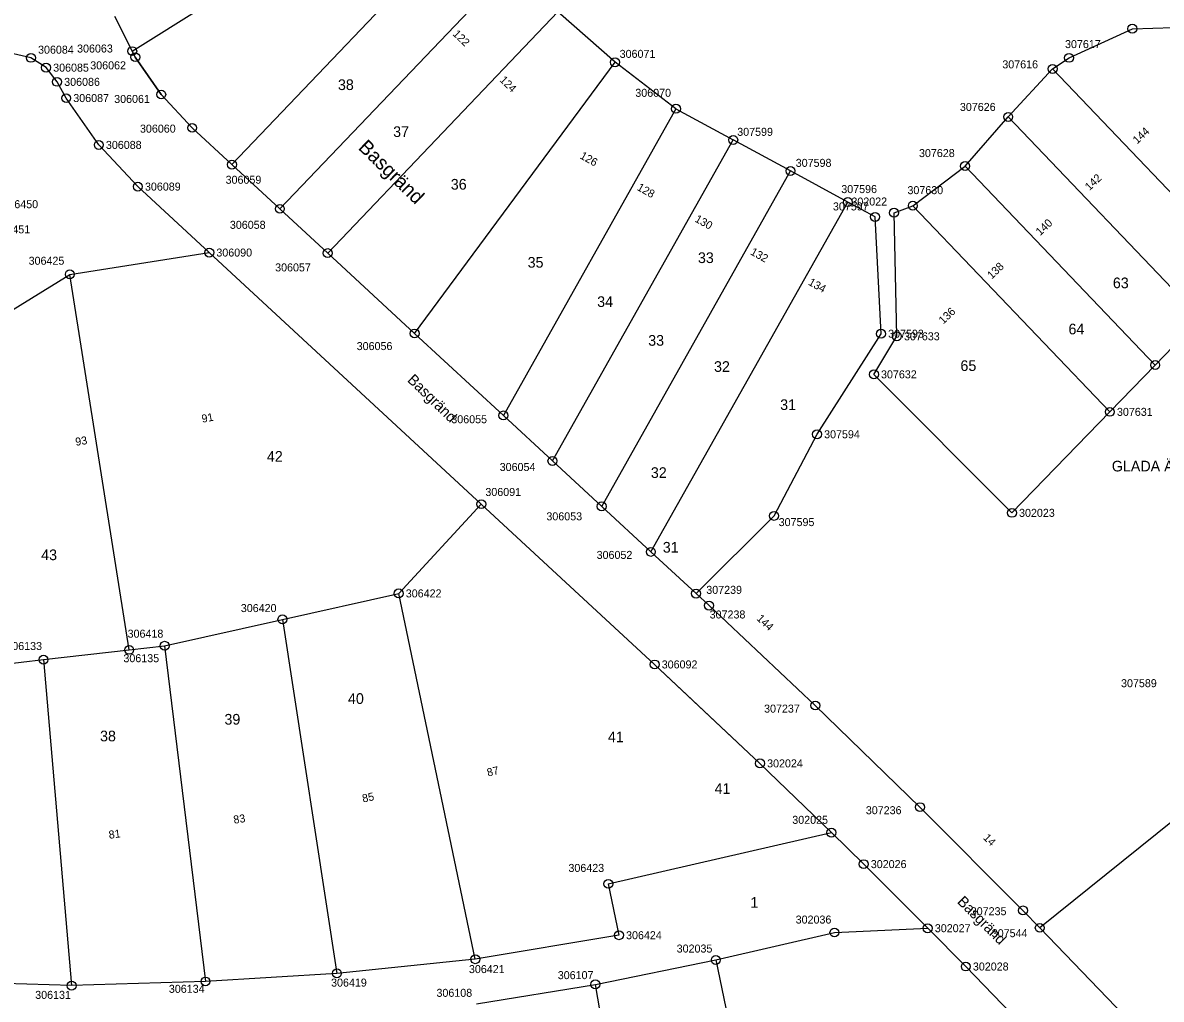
# Model space of a CAD drawing. Extents: x 141995 to 152570, y 6580184 to 6586000.
# Drawn here: x 142151.4 to 142279.5, y 6585489.3 to 6585599.2 of the extents above; entities that cross this region are included whole.
import ezdxf

# ---------------------------------------------------------------- set-up
doc = ezdxf.new("R2010")
doc.units = 0
for name, color, linetype in [('Level 10', 7, 'Continuous'), ('Level 40', 7, 'Continuous'), ('Level 42', 7, 'Continuous'), ('Level 43', 7, 'Continuous'), ('Level 5', 7, 'Continuous'), ('Level 50', 7, 'Continuous'), ('Level 51', 7, 'Continuous'), ('Level 53', 7, 'Continuous'), ('Level 54', 7, 'Continuous'), ('Level 55', 7, 'Continuous'), ('Level 59', 7, 'Continuous'), ('Level 6', 7, 'Continuous'), ('Level 7', 7, 'Continuous')]:
    doc.layers.add(name, color=color, linetype=linetype)

msp = doc.modelspace()

# ---------------------------------------------------------------- linework, layer by layer
at = {"layer": 'Level 10'}
for centre in [(142276.21, 6585598.48), (142163.75, 6585595.96), (142164.09, 6585595.28), (142152.36, 6585595.2), (142154.06, 6585594.1), (142218.04, 6585594.7), (142267.24, 6585593.96), (142269.09, 6585595.2), (142155.3, 6585592.5), (142156.32, 6585590.67), (142167.01, 6585591.08), (142224.89, 6585589.48), (142262.25, 6585588.56), (142170.49, 6585587.33), (142159.99, 6585585.41), (142231.33, 6585585.97), (142174.96, 6585583.19), (142237.77, 6585582.48), (142257.4, 6585583.03), (142164.38, 6585580.72), (142244.22, 6585578.98), (142180.35, 6585578.22), (142247.28, 6585577.31), (142249.41, 6585577.78), (142251.52, 6585578.57), (142172.41, 6585573.3), (142185.73, 6585573.24), (142156.73, 6585570.85), (142195.5, 6585564.2), (142247.95, 6585564.17), (142249.73, 6585563.88), (142247.15, 6585559.6), (142278.78, 6585560.65), (142205.48, 6585554.98), (142273.68, 6585555.38), (142240.75, 6585552.86), (142211, 6585549.86), (142203, 6585545), (142216.54, 6585544.75), (142262.67, 6585544.02), (142235.92, 6585543.68), (142222.07, 6585539.63), (142193.71, 6585534.96), (142227.15, 6585534.94), (142228.61, 6585533.59), (142180.64, 6585532.04), (142167.39, 6585529.07), (142153.77, 6585527.51), (142163.41, 6585528.61), (142222.49, 6585526.97), (142240.56, 6585522.35), (142234.34, 6585515.84), (142252.33, 6585510.92), (142242.37, 6585508.05), (142246, 6585504.51), (142217.28, 6585502.29), (142263.91, 6585499.3), (142242.71, 6585496.82), (142253.2, 6585497.29), (142265.8, 6585497.34), (142218.48, 6585496.51), (142202.33, 6585493.81), (142229.37, 6585493.73), (142257.48, 6585492.99), (142186.76, 6585492.22), (142156.93, 6585490.84), (142171.99, 6585491.31), (142215.83, 6585490.98)]:
    msp.add_circle(centre, 0.5, dxfattribs=at)
at = {"layer": 'Level 5'}
for points in [[(142163.75, 6585595.96), (142161.78, 6585599.85)], [(142164.09, 6585595.28), (142163.75, 6585595.96)], [(142152.36, 6585595.2), (142150.39, 6585595.67)], [(142154.06, 6585594.1), (142152.36, 6585595.2)], [(142167.01, 6585591.08), (142164.09, 6585595.28)], [(142155.3, 6585592.5), (142154.06, 6585594.1)], [(142156.32, 6585590.67), (142155.3, 6585592.5)], [(142159.99, 6585585.41), (142156.32, 6585590.67)], [(142170.49, 6585587.33), (142167.01, 6585591.08)], [(142174.96, 6585583.19), (142170.49, 6585587.33)], [(142164.38, 6585580.72), (142159.99, 6585585.41)], [(142180.35, 6585578.22), (142174.96, 6585583.19)], [(142172.41, 6585573.3), (142164.38, 6585580.72)], [(142185.73, 6585573.24), (142180.35, 6585578.22)], [(142172.41, 6585573.3), (142203, 6585545)], [(142195.5, 6585564.2), (142185.73, 6585573.24)], [(142205.48, 6585554.98), (142195.5, 6585564.2)], [(142211, 6585549.86), (142205.48, 6585554.98)], [(142216.54, 6585544.75), (142211, 6585549.86)], [(142203, 6585545), (142222.49, 6585526.97)], [(142222.07, 6585539.63), (142216.54, 6585544.75)], [(142222.07, 6585539.63), (142227.15, 6585534.94)], [(142228.61, 6585533.59), (142227.15, 6585534.94)], [(142240.56, 6585522.35), (142228.61, 6585533.59)], [(142222.49, 6585526.97), (142234.34, 6585515.84)], [(142252.33, 6585510.92), (142240.56, 6585522.35)], [(142234.34, 6585515.84), (142242.37, 6585508.05)], [(142263.91, 6585499.3), (142252.33, 6585510.92)], [(142246, 6585504.51), (142242.37, 6585508.05)], [(142253.2, 6585497.29), (142246, 6585504.51)], [(142265.8, 6585497.34), (142263.91, 6585499.3)], [(142253.2, 6585497.29), (142257.48, 6585492.99)], [(142275.29, 6585487.49), (142265.8, 6585497.34)], [(142257.48, 6585492.99), (142268.76, 6585481.29)]]:
    msp.add_lwpolyline(points, dxfattribs=at)
at = {"layer": 'Level 6'}
for points in [[(142161.78, 6585599.85), (142163.75, 6585595.96), (142164.09, 6585595.28), (142167.01, 6585591.08), (142170.49, 6585587.33), (142174.96, 6585583.19), (142180.35, 6585578.22), (142185.73, 6585573.24), (142195.5, 6585564.2), (142205.48, 6585554.98), (142211, 6585549.86), (142216.54, 6585544.75), (142222.07, 6585539.63), (142227.15, 6585534.94), (142228.61, 6585533.59), (142240.56, 6585522.35), (142252.33, 6585510.92), (142263.91, 6585499.3), (142265.8, 6585497.34), (142275.29, 6585487.49), (142277.92, 6585484.71), (142282.99, 6585479.38)], [(142268.76, 6585481.29), (142257.48, 6585492.99), (142253.2, 6585497.29), (142246, 6585504.51), (142242.37, 6585508.05), (142234.34, 6585515.84), (142226.12, 6585523.57), (142222.49, 6585526.97), (142203, 6585545), (142172.41, 6585573.3), (142164.38, 6585580.72), (142159.99, 6585585.41), (142156.32, 6585590.67), (142155.3, 6585592.5), (142154.06, 6585594.1), (142152.36, 6585595.2), (142150.39, 6585595.67)]]:
    msp.add_lwpolyline(points, dxfattribs=at)
at = {"layer": 'Level 7'}
for points in [[(142163.75, 6585595.96), (142197.47, 6585617.09)], [(142174.96, 6585583.19), (142201.54, 6585611.05)], [(142180.35, 6585578.22), (142206.58, 6585605.71)], [(142185.73, 6585573.24), (142211.62, 6585600.38)], [(142218.04, 6585594.7), (142211.62, 6585600.38)], [(142269.09, 6585595.2), (142276.21, 6585598.48)], [(142276.21, 6585598.48), (142280.81, 6585598.61)], [(142195.5, 6585564.2), (142218.04, 6585594.7)], [(142224.89, 6585589.48), (142218.04, 6585594.7)], [(142267.24, 6585593.96), (142269.09, 6585595.2)], [(142262.25, 6585588.56), (142267.24, 6585593.96)], [(142289.01, 6585571.18), (142267.24, 6585593.96)], [(142224.89, 6585589.48), (142205.48, 6585554.98)], [(142224.89, 6585589.48), (142231.33, 6585585.97)], [(142257.4, 6585583.03), (142262.25, 6585588.56)], [(142283.89, 6585565.91), (142262.25, 6585588.56)], [(142211, 6585549.86), (142231.33, 6585585.97)], [(142237.77, 6585582.48), (142231.33, 6585585.97)], [(142251.52, 6585578.57), (142257.4, 6585583.03)], [(142278.78, 6585560.65), (142257.4, 6585583.03)], [(142216.54, 6585544.75), (142237.77, 6585582.48)], [(142244.22, 6585578.98), (142237.77, 6585582.48)], [(142222.07, 6585539.63), (142244.22, 6585578.98)], [(142247.28, 6585577.31), (142244.22, 6585578.98)], [(142249.41, 6585577.78), (142251.52, 6585578.57)], [(142273.68, 6585555.38), (142251.52, 6585578.57)], [(142247.95, 6585564.17), (142247.28, 6585577.31)], [(142249.73, 6585563.88), (142249.41, 6585577.78)], [(142156.73, 6585570.85), (142172.41, 6585573.3)], [(142148.06, 6585565.5), (142156.73, 6585570.85)], [(142163.41, 6585528.61), (142156.73, 6585570.85)], [(142283.89, 6585565.91), (142278.78, 6585560.65)], [(142240.75, 6585552.86), (142247.95, 6585564.17)], [(142247.15, 6585559.6), (142249.73, 6585563.88)], [(142278.78, 6585560.65), (142273.68, 6585555.38)], [(142262.67, 6585544.02), (142247.15, 6585559.6)], [(142273.68, 6585555.38), (142262.67, 6585544.02)], [(142235.92, 6585543.68), (142240.75, 6585552.86)], [(142193.71, 6585534.96), (142203, 6585545)], [(142227.15, 6585534.94), (142235.92, 6585543.68)], [(142180.64, 6585532.04), (142193.71, 6585534.96)], [(142202.33, 6585493.81), (142193.71, 6585534.96)], [(142167.39, 6585529.07), (142180.64, 6585532.04)], [(142180.64, 6585532.04), (142186.76, 6585492.22)], [(142153.77, 6585527.51), (142163.41, 6585528.61)], [(142163.41, 6585528.61), (142167.39, 6585529.07)], [(142167.39, 6585529.07), (142171.99, 6585491.31)], [(142148.72, 6585526.93), (142153.77, 6585527.51)], [(142153.77, 6585527.51), (142156.93, 6585490.84)], [(142284.55, 6585512.43), (142265.8, 6585497.34)], [(142217.28, 6585502.29), (142242.37, 6585508.05)], [(142217.28, 6585502.29), (142218.48, 6585496.51)], [(142242.71, 6585496.82), (142253.2, 6585497.29)], [(142218.48, 6585496.51), (142202.33, 6585493.81)], [(142229.37, 6585493.73), (142242.71, 6585496.82)], [(142202.33, 6585493.81), (142186.76, 6585492.22)], [(142215.83, 6585490.98), (142229.37, 6585493.73)], [(142229.37, 6585493.73), (142235.99, 6585461.67)], [(142186.76, 6585492.22), (142171.99, 6585491.31)], [(142156.93, 6585490.84), (142141.82, 6585491.3)], [(142171.99, 6585491.31), (142156.93, 6585490.84)], [(142202.46, 6585488.79), (142215.83, 6585490.98)], [(142221.27, 6585459.13), (142215.83, 6585490.98)]]:
    msp.add_lwpolyline(points, dxfattribs=at)

# ---------------------------------------------------------------- texts
at = {"layer": 'Level 40'}
msp.add_text('Basgränd', height=1.2, rotation=315.7505, dxfattribs=at).set_placement((142194.61, 6585558.88))
at = {"layer": 'Level 42'}
msp.add_text('Basgränd', height=1.2, rotation=315.0514, dxfattribs=at).set_placement((142256.44, 6585500.2))
at = {"layer": 'Level 43'}
msp.add_text('Basgränd', height=1.6, rotation=315.7505, dxfattribs=at).set_placement((142189.07, 6585585.01))
at = {"layer": 'Level 50'}
msp.add_text('GLADA ÄNKAN', height=1.2, rotation=0.0527, dxfattribs=at).set_placement((142273.9, 6585548.68))
at = {"layer": 'Level 51'}
for s, p in [('38', (142186.88, 6585591.58)), ('37', (142193.09, 6585586.3)), ('36', (142199.57, 6585580.38)), ('35', (142208.21, 6585571.6)), ('63', (142274.02, 6585569.29)), ('34', (142216.03, 6585567.18)), ('64', (142269.03, 6585564.1)), ('33', (142221.77, 6585562.82)), ('65', (142256.88, 6585559.98)), ('32', (142229.17, 6585559.88)), ('31', (142236.61, 6585555.59)), ('42', (142178.89, 6585549.77)), ('43', (142153.51, 6585538.7)), ('40', (142188.01, 6585522.53)), ('39', (142174.12, 6585520.2)), ('38', (142160.13, 6585518.32)), ('41', (142217.24, 6585518.22)), ('1', (142233.26, 6585499.6))]:
    msp.add_text(s, height=1.2, rotation=0.0527, dxfattribs=at).set_placement(p)
at = {"layer": 'Level 53'}
for s, p in [('307617', (142268.64, 6585596.3)), ('306084', (142153.16, 6585595.67)), ('306063', (142157.55, 6585595.8)), ('306071', (142218.56, 6585595.2)), ('306085', (142154.86, 6585593.65)), ('306062', (142159.03, 6585593.91)), ('307616', (142261.59, 6585594.02)), ('306086', (142156.1, 6585592.05)), ('306087', (142157.12, 6585590.23)), ('306061', (142161.72, 6585590.13)), ('306070', (142220.32, 6585590.82)), ('307626', (142256.82, 6585589.23)), ('306060', (142164.62, 6585586.79)), ('307599', (142231.78, 6585586.43)), ('306088', (142160.79, 6585584.96)), ('307628', (142252.22, 6585584.04)), ('307598', (142238.36, 6585582.94)), ('306059', (142174.25, 6585581.04)), ('306089', (142165.18, 6585580.27)), ('307596', (142243.48, 6585579.99)), ('307630', (142250.92, 6585579.87)), ('306450', (142149.15, 6585578.29)), ('302022', (142244.62, 6585578.59)), ('307597', (142242.54, 6585578.04)), ('306058', (142174.73, 6585575.97)), ('306451', (142148.26, 6585575.46)), ('306425', (142152.1, 6585571.93)), ('306090', (142173.21, 6585572.85)), ('306057', (142179.82, 6585571.18)), ('307593', (142248.75, 6585563.72)), ('307633', (142250.53, 6585563.43)), ('306056', (142188.99, 6585562.33)), ('307632', (142247.95, 6585559.15)), ('306055', (142199.63, 6585554.1)), ('307631', (142274.48, 6585554.93)), ('307594', (142241.55, 6585552.41)), ('306054', (142205.07, 6585548.73)), ('306091', (142203.46, 6585545.92)), ('306053', (142210.32, 6585543.18)), ('307595', (142236.44, 6585542.53)), ('302023', (142263.47, 6585543.57)), ('306052', (142215.97, 6585538.84)), ('307239', (142228.3, 6585534.91)), ('306422', (142194.51, 6585534.51)), ('306420', (142175.96, 6585532.86)), ('307238', (142228.68, 6585532.14)), ('306418', (142163.23, 6585529.98)), ('306133', (142149.59, 6585528.59)), ('306135', (142162.76, 6585527.22)), ('306092', (142223.29, 6585526.52)), ('307589', (142274.94, 6585524.41)), ('307237', (142234.8, 6585521.55)), ('302024', (142235.14, 6585515.39)), ('302025', (142237.97, 6585509.04)), ('307236', (142246.24, 6585510.12)), ('302026', (142246.8, 6585504.06)), ('306423', (142212.8, 6585503.63)), ('302036', (142238.35, 6585497.82)), ('307235', (142258.04, 6585498.76)), ('302027', (142254, 6585496.85)), ('307544', (142260.4, 6585496.29)), ('306424', (142219.28, 6585496.06)), ('302035', (142224.97, 6585494.56)), ('302028', (142258.28, 6585492.54)), ('306421', (142201.61, 6585492.25)), ('306107', (142211.6, 6585491.57)), ('306134', (142167.87, 6585490.03)), ('306419', (142186.11, 6585490.73)), ('306131', (142152.84, 6585489.35)), ('306108', (142197.96, 6585489.58))]:
    msp.add_text(s, height=0.9, rotation=0.0527, dxfattribs=at).set_placement(p)
at = {"layer": 'Level 54'}
for s, rotation, p in [('122', 315.5115, (142199.73, 6585597.82)), ('124', 315.5115, (142204.99, 6585592.64)), ('144', 43.2716, (142276.76, 6585585.46)), ('126', 330.6411, (142214.01, 6585583.94)), ('142', 43.2716, (142271.38, 6585580.21)), ('128', 330.6411, (142220.43, 6585580.38)), ('130', 330.6411, (142226.93, 6585576.83)), ('140', 43.2716, (142265.85, 6585575.15)), ('132', 330.6401, (142233.18, 6585573.13)), ('138', 43.2716, (142260.39, 6585570.26)), ('134', 330.6401, (142239.69, 6585569.72)), ('136', 43.2716, (142254.94, 6585565.19)), ('91', 10.6977, (142171.64, 6585554.15)), ('93', 9.0157, (142157.42, 6585551.56)), ('87', 13.4606, (142203.75, 6585514.35)), ('85', 11.7776, (142189.71, 6585511.44)), ('83', 8.7117, (142175.2, 6585509.05)), ('81', 7.1157, (142161.16, 6585507.36))]:
    msp.add_text(s, height=0.9, rotation=rotation, dxfattribs=at).set_placement(p)
at = {"layer": 'Level 55'}
for s, rotation, p in [('144', 316.7555, (142233.89, 6585532.05)), ('14', 314.9034, (142259.37, 6585507.4))]:
    msp.add_text(s, height=0.9, rotation=rotation, dxfattribs=at).set_placement(p)
at = {"layer": 'Level 59'}
for s, p in [('33', (142227.36, 6585572.12)), ('32', (142222.07, 6585547.95)), ('31', (142223.41, 6585539.55)), ('41', (142229.23, 6585512.41))]:
    msp.add_text(s, height=1.2, rotation=0.0527, dxfattribs=at).set_placement(p)

doc.saveas('drawing.dxf')
